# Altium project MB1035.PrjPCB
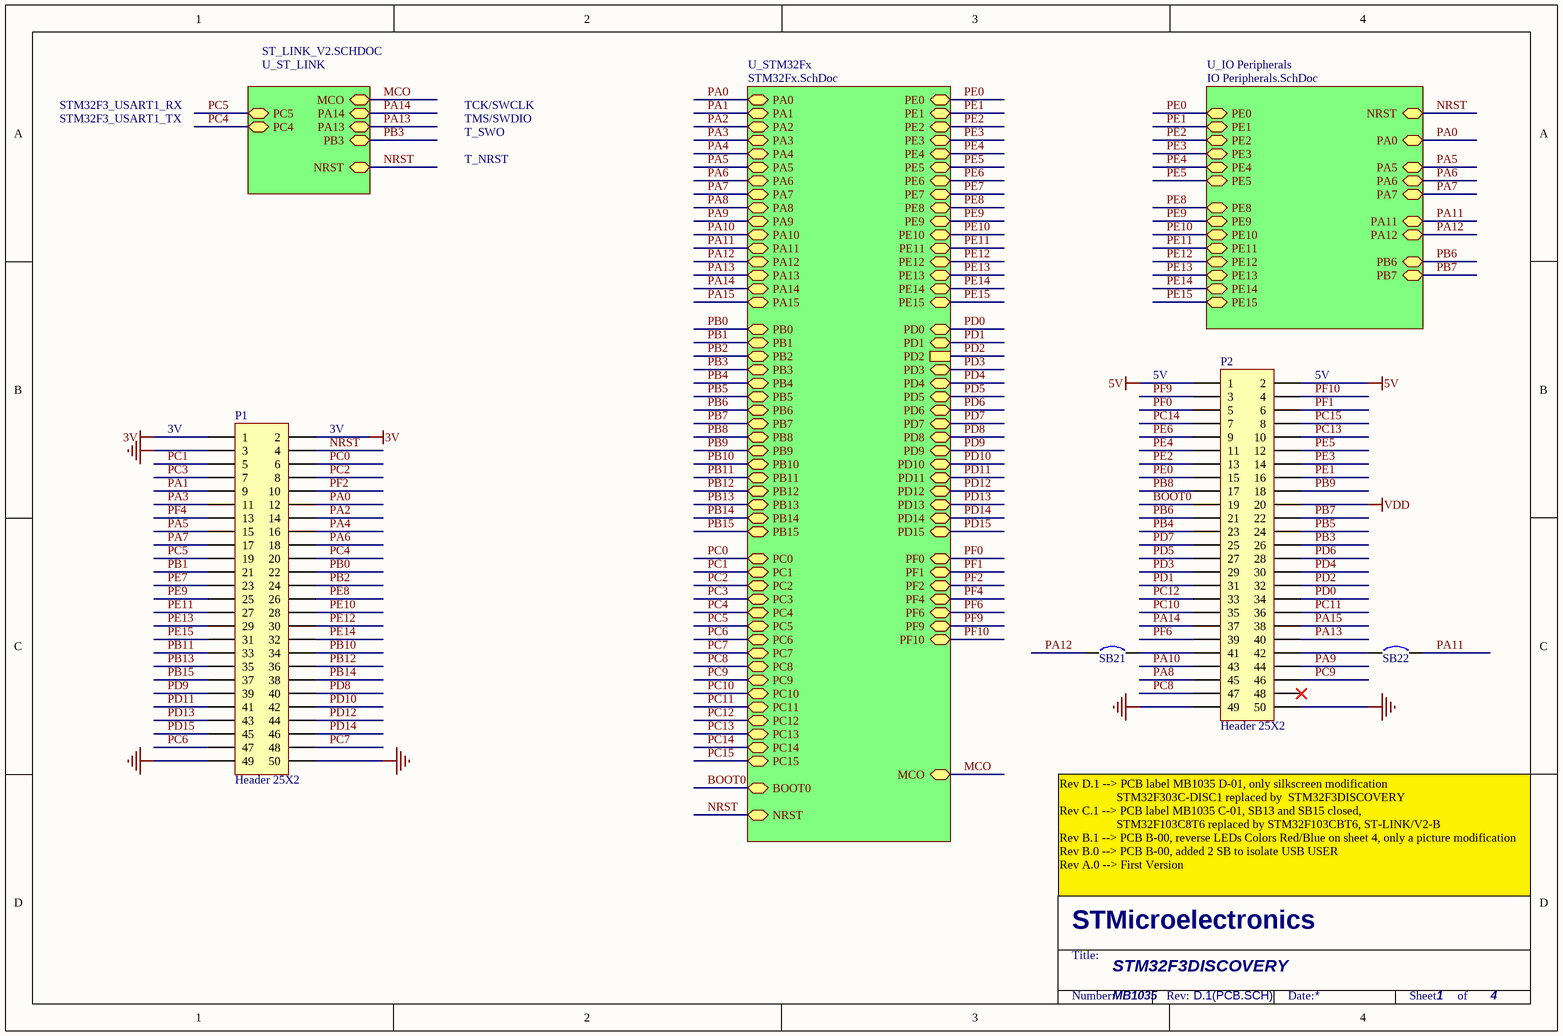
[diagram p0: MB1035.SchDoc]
4 sheets, 145 parts. Net scope: hierarchical (ports join the sheet entries above them; power ports are global).
Board file: MB1035B.PCBDOC
Sheets:
  MB1035.SchDoc
    U_ST_LINK = ST_LINK_V2.SCHDOC
    U_IO Peripherals = IO Peripherals.SchDoc
    U_STM32Fx = STM32Fx.SchDoc

## Sheet MB1035.SchDoc
size A4; DocumentNumber: 1; Revision: D.1(PCB.SCH); SheetNumber: 1; SheetTotal: 4; PageSetup: Record=PageOptions|CenterHorizontal=True|CenterVertical=True|PrintScale=1.00|XCorrection=1.00|YCorrection=1.00|PrintKind=1|BorderSize=5000000|LeftOffset=0|BottomOffset=0|Orientation=2|PaperLength=1000|PaperWidth=1000|Scale=100|PaperSource=15|PrintQuality=1200|MediaType=1|DitherType=10|PaperKind=A4|PrintScaleMode=1

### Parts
P1  Header 25X2  [HEAD25X2/2.54]
P2  Header 25X2  [HEAD25X2/2.54]
SB21  Circuit Breaker  [JP2_SMD]  (value not drawn)
SB22  Circuit Breaker  [JP2_SMD]  (value not drawn)

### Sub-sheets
U_IO Peripherals = IO Peripherals.SchDoc: PA0, NRST, PE0, PE1, PE3, PA5, PA7, PA6, PB6, PB7, PE4, PE5, PE2, PE8, PE15, PA11, PA12, PE9, PE10, PE11, PE12, PE13, PE14
U_ST_LINK = ST_LINK_V2.SCHDOC: PA13, PA14, NRST, PC5, PC4, PB3, MCO
U_STM32Fx = STM32Fx.SchDoc: PB8, PC5, PC4, PD2, BOOT0, NRST, PE0, PE1, PE2, PE3, PE4, PE5, PE6, PE7, PE8, PE9, PE10, PE11, PE12, PE13, PE14, PE15, PD0, PD1, PD3, PD4, PD5, PD6, PD7, PD8, PD9, PD10, PD11, PD12, PD13, PD14, PD15, PC15, PC14, PF1, PF0, MCO, PF2, PF4, PF6, PF9, PF10, PC0, PC1, PC2, PC3, PC6, PC7, PC8, PC9, PC10, PC11, PC12, PC13, PA0, PA1, PA2, PA3, PA4, PA5, PA6, PA7, PA8, PA9, PA10, PA11, PA12, PA13, PA14, PA15, PB0, PB1, PB2, PB3, PB4, PB5, PB6, PB7, PB9, PB10, PB11, PB12, PB13, PB14, PB15

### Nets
3V: P1.1 P1.2
5V: P2.1 P2.2
GND: P1.3 P1.49 P1.50 P2.49 P2.50
VDD: P2.20
BOOT0: P2.19 ; sheet U_STM32Fx/BOOT0
MCO: sheet U_ST_LINK/MCO, sheet U_STM32Fx/MCO
NRST: P1.4 ; sheet U_ST_LINK/NRST, sheet U_IO Peripherals/NRST, sheet U_STM32Fx/NRST
PA0: P1.12 ; sheet U_IO Peripherals/PA0, sheet U_STM32Fx/PA0
PA1: P1.9 ; sheet U_STM32Fx/PA1
PA2: P1.14 ; sheet U_STM32Fx/PA2
PA3: P1.11 ; sheet U_STM32Fx/PA3
PA4: P1.16 ; sheet U_STM32Fx/PA4
PA5: P1.15 ; sheet U_IO Peripherals/PA5, sheet U_STM32Fx/PA5
PA6: P1.18 ; sheet U_IO Peripherals/PA6, sheet U_STM32Fx/PA6
PA7: P1.17 ; sheet U_IO Peripherals/PA7, sheet U_STM32Fx/PA7
PA8: P2.45 ; sheet U_STM32Fx/PA8
PA9: P2.44 ; sheet U_STM32Fx/PA9
PA10: P2.43 ; sheet U_STM32Fx/PA10
PA11: SB22.2 ; sheet U_IO Peripherals/PA11, sheet U_STM32Fx/PA11
PA12: SB21.1 ; sheet U_IO Peripherals/PA12, sheet U_STM32Fx/PA12
PA13: P2.40 ; sheet U_ST_LINK/PA13, sheet U_STM32Fx/PA13
PA14: P2.37 ; sheet U_ST_LINK/PA14, sheet U_STM32Fx/PA14
PA15: P2.38 ; sheet U_STM32Fx/PA15
PB0: P1.22 ; sheet U_STM32Fx/PB0
PB1: P1.21 ; sheet U_STM32Fx/PB1
PB2: P1.24 ; sheet U_STM32Fx/PB2
PB3: P2.26 ; sheet U_ST_LINK/PB3, sheet U_STM32Fx/PB3
PB4: P2.23 ; sheet U_STM32Fx/PB4
PB5: P2.24 ; sheet U_STM32Fx/PB5
PB6: P2.21 ; sheet U_IO Peripherals/PB6, sheet U_STM32Fx/PB6
PB7: P2.22 ; sheet U_IO Peripherals/PB7, sheet U_STM32Fx/PB7
PB8: P2.17 ; sheet U_STM32Fx/PB8
PB9: P2.18 ; sheet U_STM32Fx/PB9
PB10: P1.34 ; sheet U_STM32Fx/PB10
PB11: P1.33 ; sheet U_STM32Fx/PB11
PB12: P1.36 ; sheet U_STM32Fx/PB12
PB13: P1.35 ; sheet U_STM32Fx/PB13
PB14: P1.38 ; sheet U_STM32Fx/PB14
PB15: P1.37 ; sheet U_STM32Fx/PB15
PC0: P1.6 ; sheet U_STM32Fx/PC0
PC1: P1.5 ; sheet U_STM32Fx/PC1
PC2: P1.8 ; sheet U_STM32Fx/PC2
PC3: P1.7 ; sheet U_STM32Fx/PC3
PC4: P1.20 ; sheet U_ST_LINK/PC4, sheet U_STM32Fx/PC4
PC5: P1.19 ; sheet U_ST_LINK/PC5, sheet U_STM32Fx/PC5
PC6: P1.47 ; sheet U_STM32Fx/PC6
PC7: P1.48 ; sheet U_STM32Fx/PC7
PC8: P2.47 ; sheet U_STM32Fx/PC8
PC9: P2.46 ; sheet U_STM32Fx/PC9
PC10: P2.35 ; sheet U_STM32Fx/PC10
PC11: P2.36 ; sheet U_STM32Fx/PC11
PC12: P2.33 ; sheet U_STM32Fx/PC12
PC13: P2.10 ; sheet U_STM32Fx/PC13
PC14: P2.7 ; sheet U_STM32Fx/PC14
PC15: P2.8 ; sheet U_STM32Fx/PC15
PD0: P2.34 ; sheet U_STM32Fx/PD0
PD1: P2.31 ; sheet U_STM32Fx/PD1
PD2: P2.32 ; sheet U_STM32Fx/PD2
PD3: P2.29 ; sheet U_STM32Fx/PD3
PD4: P2.30 ; sheet U_STM32Fx/PD4
PD5: P2.27 ; sheet U_STM32Fx/PD5
PD6: P2.28 ; sheet U_STM32Fx/PD6
PD7: P2.25 ; sheet U_STM32Fx/PD7
PD8: P1.40 ; sheet U_STM32Fx/PD8
PD9: P1.39 ; sheet U_STM32Fx/PD9
PD10: P1.42 ; sheet U_STM32Fx/PD10
PD11: P1.41 ; sheet U_STM32Fx/PD11
PD12: P1.44 ; sheet U_STM32Fx/PD12
PD13: P1.43 ; sheet U_STM32Fx/PD13
PD14: P1.46 ; sheet U_STM32Fx/PD14
PD15: P1.45 ; sheet U_STM32Fx/PD15
PE0: P2.15 ; sheet U_IO Peripherals/PE0, sheet U_STM32Fx/PE0
PE1: P2.16 ; sheet U_IO Peripherals/PE1, sheet U_STM32Fx/PE1
PE2: P2.13 ; sheet U_IO Peripherals/PE2, sheet U_STM32Fx/PE2
PE3: P2.14 ; sheet U_IO Peripherals/PE3, sheet U_STM32Fx/PE3
PE4: P2.11 ; sheet U_IO Peripherals/PE4, sheet U_STM32Fx/PE4
PE5: P2.12 ; sheet U_IO Peripherals/PE5, sheet U_STM32Fx/PE5
PE6: P2.9 ; sheet U_STM32Fx/PE6
PE7: P1.23 ; sheet U_STM32Fx/PE7
PE8: P1.26 ; sheet U_IO Peripherals/PE8, sheet U_STM32Fx/PE8
PE9: P1.25 ; sheet U_IO Peripherals/PE9, sheet U_STM32Fx/PE9
PE10: P1.28 ; sheet U_IO Peripherals/PE10, sheet U_STM32Fx/PE10
PE11: P1.27 ; sheet U_IO Peripherals/PE11, sheet U_STM32Fx/PE11
PE12: P1.30 ; sheet U_IO Peripherals/PE12, sheet U_STM32Fx/PE12
PE13: P1.29 ; sheet U_IO Peripherals/PE13, sheet U_STM32Fx/PE13
PE14: P1.32 ; sheet U_IO Peripherals/PE14, sheet U_STM32Fx/PE14
PE15: P1.31 ; sheet U_IO Peripherals/PE15, sheet U_STM32Fx/PE15
PF0: P2.5 ; sheet U_STM32Fx/PF0
PF1: P2.6 ; sheet U_STM32Fx/PF1
PF2: P1.10 ; sheet U_STM32Fx/PF2
PF4: P1.13 ; sheet U_STM32Fx/PF4
PF6: P2.39 ; sheet U_STM32Fx/PF6
PF9: P2.3 ; sheet U_STM32Fx/PF9
PF10: P2.4 ; sheet U_STM32Fx/PF10
NetP2_41: P2.41 SB21.2
NetP2_42: P2.42 SB22.1

Not connected (* = marked no-connect by the designer): P2 48*

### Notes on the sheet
- STM32F3_USART1_RX
- TCK/SWCLK
- STM32F3_USART1_TX
- TMS/SWDIO
- T_SWO
- T_NRST
- 5V
- (near P2) 5V
- 3V
- (near P1) 3V
- Rev D.1 --> PCB label MB1035 D-01, only silkscreen modification
  STM32F303C-DISC1 replaced by  STM32F3DISCOVERY
  Rev C.1 --> PCB label MB1035 C-01, SB13 and SB15 closed,
  STM32F103C8T6 replaced by STM32F103CBT6, ST-LINK/V2-B
  Rev B.1 --> PCB B-00, reverse LEDs Colors Red/Blue on sheet 4, only a picture modification
  Rev B.0 --> PCB B-00, added 2 SB to isolate USB USER
  Rev A.0 --> First Version
- STM32F3DISCOVERY
- MB1035
- 1

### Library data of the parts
P1 P2 = Header 25X2: Header, 25-Pin, Dual row
SB21 SB22 = Circuit Breaker: Solder: NO

## Sheet ST_LINK_V2.SCHDOC
size A4; DocumentNumber: 2; Revision: D.1(PCB.SCH); SheetNumber: 2; SheetTotal: 4
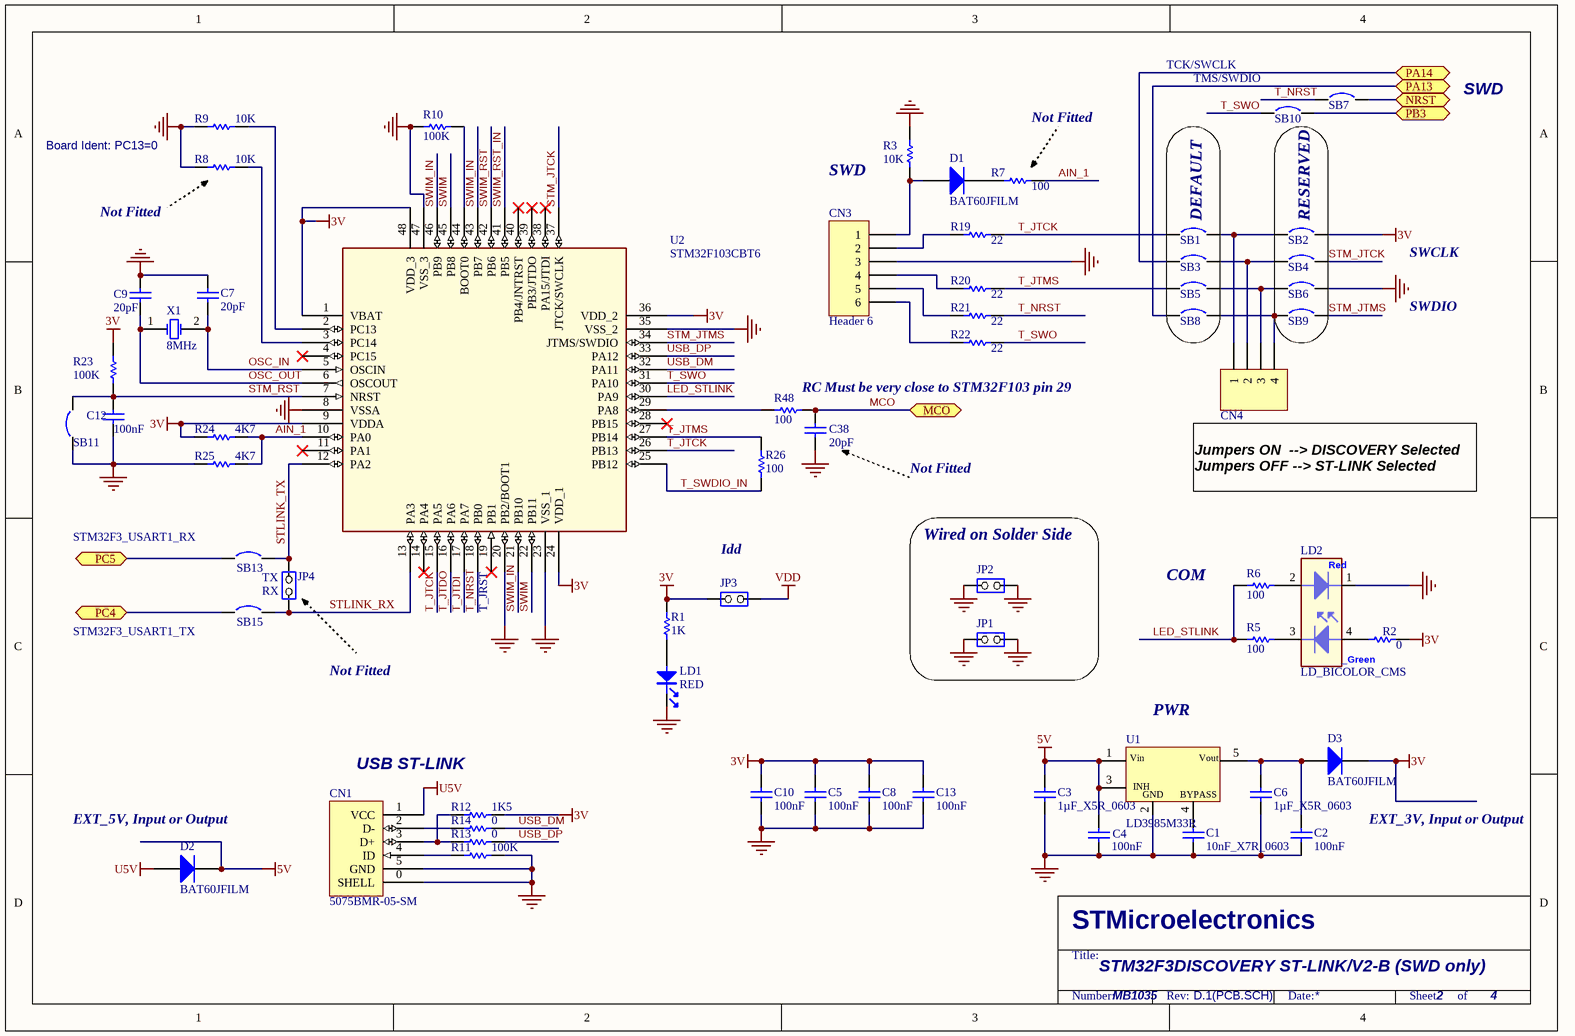
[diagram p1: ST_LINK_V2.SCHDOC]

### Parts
C1  10nF_X7R_0603  [0603C]
C2  100nF  [0603C]
C3  1µF_X5R_0603  [0603C]
C4  100nF  [0603C]
C5  100nF  [0402C]
C6  1µF_X5R_0603  [0603C]
C7  20pF  [0402C]
C8  100nF  [0402C]
C9  20pF  [0402C]
C10  100nF  [0402C]
C12  100nF  [0402C]
C13  100nF  [0402C]
C38  20pF  [0402C]
CN1  5075BMR-05-SM  [USB-MINI-B-SMD]
CN3  Header 6  [HDR1X6]
CN4  Header 4  [Header 4]  (value not drawn)
D1  BAT60JFILM  [SOD323/A]
D2  BAT60JFILM  [SOD323/A]
D3  BAT60JFILM  [SOD323/A]
JP1  (no value)  [SIP2/2.54]
JP2  (no value)  [SIP2/2.54]
JP3  (no value)  [SIP2/2.54]
JP4  JP2  [SIP2/2.54]  (value not drawn)
LD1  RED  [0603D]
LD2  LD_BICOLOR_CMS  [HSMF-A201]
R1  1K  [0402R]
R2  0  [0402R]
R3  10K  [0402R]
R5  100  [0402R]
R6  100  [0402R]
R7  100  [0402R]
R8  10K  [0402R]
R9  10K  [0402R]
R10  100K  [0402R]
R11  100K  [0402R]
R12  1K5  [0402R]
R13  0  [0402R]
R14  0  [0402R]
R19  22  [0402R]
R20  22  [0402R]
R21  22  [0402R]
R22  22  [0402R]
R23  100K  [0402R]
R24  4K7  [0402R]
R25  4K7  [0402R]
R26  100  [0402R]
R48  100  [0402R]
SB1  Circuit Breaker  [JP2_SMD]  (value not drawn)
SB2  Circuit Breaker  [JP2_SMD]  (value not drawn)
SB3  Circuit Breaker  [JP2_SMD]  (value not drawn)
SB4  Circuit Breaker  [JP2_SMD]  (value not drawn)
SB5  Circuit Breaker  [JP2_SMD]  (value not drawn)
SB6  Circuit Breaker  [JP2_SMD]  (value not drawn)
SB7  Circuit Breaker  [JP2_SMD]  (value not drawn)
SB8  Circuit Breaker  [JP2_SMD]  (value not drawn)
SB9  Circuit Breaker  [JP2_SMD]  (value not drawn)
SB10  Circuit Breaker  [JP2_SMD]  (value not drawn)
SB11  Circuit Breaker  [JP2_SMD]  (value not drawn)
SB13  Circuit Breaker  [JP2_SMD]  (value not drawn)
SB15  Circuit Breaker  [JP2_SMD]  (value not drawn)
U1  LD3985M33R  [SOT-23-5L]
U2  STM32F103CBT6  [QFP48 7x7]
X1  8MHz  [XTAL1]

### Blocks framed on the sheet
DEFAULT: SB1 SB3 SB5 SB8
RESERVED: SB2 SB4 SB6 SB9
Wired on Solder Side: JP1 JP2

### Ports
MCO, NRST, PA13, PA14, PB3, PC4, PC5

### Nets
3V: C5.2 C8.1 C10.2 C13.2 D3.2(K) JP3.1(COMMON) R1.2 R2.2 R12.2 R23.2 R24.1 SB2.2 U2.1(VBAT) U2.9(VDDA) U2.24(VDD_1) U2.36(VDD_2) U2.48(VDD_3)
5V: C3.2 C4.2 D2.2(K) U1.1(Vin) U1.3(CE)
GND: C1.1 C2.1 C3.1 C4.1 C5.1 C6.2 C7.1 C8.2 C9.1 C10.1 C12.1 C13.1 C38.2 CN1.0(SHELL) CN1.5(GND) CN3.3 JP1.1(COMMON) JP1.2(NO) JP2.1(COMMON) JP2.2(NO) LD1.2 LD2.1 R3.2 R8.1 R9.1 R10.1 R11.2 R25.1 SB6.2 SB11.1 U1.2(GND) U2.8(VSSA) U2.20(PB2/BOOT1) U2.23(VSS_1) U2.35(VSS_2) U2.47(VSS_3)
U5V: CN1.1(VCC) D2.1(A)
VDD: JP3.2(NO)
AIN_1: R7.2 R24.2 R25.2 U2.10(PA0)
LED_STLINK: R5.1 R6.1 U2.30(PA9)
MCO: C38.1 R48.2 ; port MCO
NRST: SB7.2 ; port NRST
OSC_IN: C7.2 U2.5(OSCIN) X1.2(OSC2)
OSC_OUT: C9.2 U2.6(OSCOUT) X1.1(OSC1)
PA13: SB8.1 ; port PA13
PA14: SB3.1 ; port PA14
PB3: SB10.2 ; port PB3
PC4: SB15.1 ; port PC4
PC5: SB13.1 ; port PC5
STLINK_RX: JP4.1(COMMON) SB15.2 U2.13(PA3)
STLINK_TX: JP4.2(NO) SB13.2 U2.12(PA2)
STM_JTCK: SB4.2 U2.37(JTCK/SWCLK)
STM_JTMS: SB9.2 U2.34(JTMS/SWDIO)
STM_RST: C12.2 R23.1 SB11.2 U2.7(NRST)
SWIM: U2.22(PB11) U2.45(PB8)
SWIM_IN: U2.21(PB10) U2.43(PB7) U2.46(PB9)
SWIM_RST: U2.42(PB6)
SWIM_RST_IN: U2.41(PB5)
T_JTCK: R19.2 SB1.1 U2.15(PA5) U2.26(PB13)
T_JTDI: U2.17(PA7)
T_JTDO: U2.16(PA6)
T_JTMS: R20.2 R26.2 SB5.1 U2.27(PB14)
T_NRST: R21.2 SB7.1 U2.18(PB0)
T_SWDIO_IN: R26.1 U2.25(PB12)
T_SWO: R22.2 SB10.1 U2.31(PA10)
USB_DM: R14.2 U2.32(PA11)
USB_DP: R13.2 U2.33(PA12)
NetC1_2: C1.2 U1.4(BYPASS)
NetC2_2: C2.2 C6.1 D3.1(A) U1.5(Vout)
NetCN1_2: CN1.2(D-) R14.1
NetCN1_3: CN1.3(D+) R12.1 R13.1
NetCN1_4: CN1.4(ID) R11.1
NetCN3_1: CN3.1 D1.1(A) R3.1
NetCN3_2: CN3.2 R19.1
NetCN3_4: CN3.4 R20.1
NetCN3_5: CN3.5 R21.1
NetCN3_6: CN3.6 R22.1
NetCN4_1: CN4.1 SB1.2 SB2.1
NetCN4_2: CN4.2 SB3.2 SB4.1
NetCN4_3: CN4.3 SB5.2 SB6.1
NetCN4_4: CN4.4 SB8.2 SB9.1
NetD1_2: D1.2(K) R7.1
NetLD1_1: LD1.1 R1.1
NetLD2_2: LD2.2 R6.2
NetLD2_3: LD2.3 R5.2
NetLD2_4: LD2.4 R2.1
NetR8_2: R8.2 U2.3(PC14)
NetR9_2: R9.2 U2.2(PC13)
NetR10_2: R10.2 U2.44(BOOT0)
NetR48_1: R48.1 U2.29(PA8)

Not connected (* = marked no-connect by the designer): U2 4(PC15)* 11(PA1)* 14(PA4)* 19(PB1)* 28(PB15)* 38(PA15/JTDI)* 39(PB3/JTDO)* 40(PB4/JNTRST)*

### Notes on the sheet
- TCK/SWCLK
- (near SB10) TMS/SWDIO
- SWD
- Board Ident: PC13=0
- Not Fitted
- SWCLK
- SWDIO
- (near R48) RC Must be very close to STM32F103 pin 29
- Jumpers ON  --> DISCOVERY Selected
  Jumpers OFF --> ST-LINK Selected
- STM32F3_USART1_RX
- TX
- (near JP3) Idd
- COM
- STM32F3_USART1_TX
- RX
- (near U2) T_JRST
- (near U1) PWR
- USB ST-LINK
- (near D2) EXT_5V, Input or Output
- EXT_3V, Input or Output
- STM32F3DISCOVERY ST-LINK/V2-B (SWD only)
- MB1035

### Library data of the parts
C1 = CAP SMD 0603  X7R 10000PF 50V 10%: 0603  X7R 10NF; Order code RS: 2040779; Rated voltage: 50V; Tolerance: 10%
C2 C4 C5 C7-C10 C12 C13 = Cap: Capacitor
C3 C6 = CAP SMD 0603  X5R 1µF 25V 10%: 0603  X5R 1µF; Rated voltage: 25V; Tolerance: 10%
C38 = Cap: Capacitor; Fitted: NO
CN1 = USB-MINI-typeB connector
CN3 = Header 6: Header, 6-Pin
CN4 = Header 4: Header, 4-Pin
D1-D3 = BAT60JFILM: Manuf_1: STM; Code - JEDEC: DO-214-AB; Provided: ST
JP1-JP3 = JP2
JP4 = JP2: Fitted: NO
LD1 = PHOTO
LD2 = LD_BICOLOR_CMS: Bicolor Led; Manuf_Part_1: HSMF-A201-A00J1; Manuf_1: Avago Technologies; Ref St: xxxxxx; cap_dec: ----
R1-R3 R5 R6 R9-R12 R19-R26 R48 = res1: Resistor
R7 R8 = res1: Resistor; Fitted: NO
R13 R14 = res1: Resistor; Value: 1K5
SB1 SB3 SB5 SB8 SB10 SB11 = Circuit Breaker: Solder: NO
SB2 SB4 SB6 SB7 SB9 = Circuit Breaker: Solder: YES
U1 = LD3985M33R: Ultra low drop-low noise BiCMOS voltage, regulators low ESR capacitors compatible; Manuf_1: STM; Provided: ST; Ref St: 9176161
U2 = STM32F103CBT6: Medium-density performance line ARM-based 32-bit MCU with 128KB Flash; Manuf_1: STM; Ref St: xxxxxxxx; Provided: ST; ECCN_US/EU: 3A991A2/NEC
X1 = XTAL: Crystal Oscillator

## Sheet IO Peripherals.SchDoc
size A4; DocumentNumber: 6; Revision: D.1(PCB.SCH); SheetNumber: 4; SheetTotal: 4
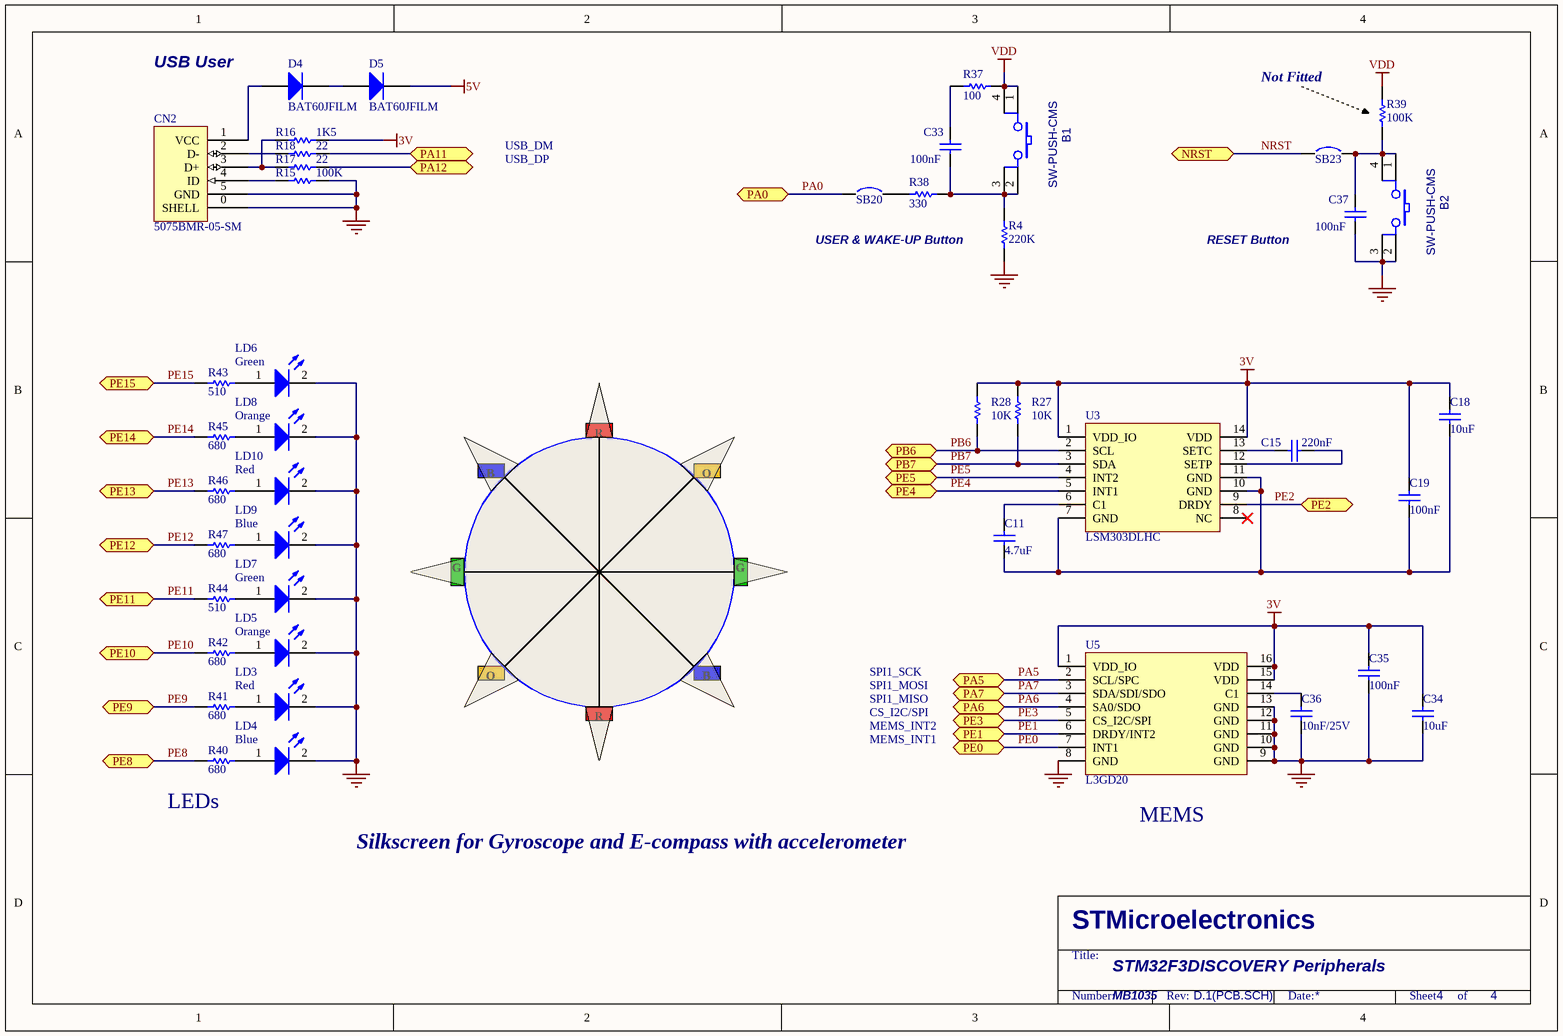
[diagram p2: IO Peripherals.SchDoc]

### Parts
B1  SW-PUSH-CMS  [BP1CMS]
B2  SW-PUSH-CMS  [BP1CMS]
C11  4.7uF  [0603C]
C15  220nF  [0603C]
C18  10uF  [0603C]
C19  100nF  [0603C]
C33  100nF  [0603C]
C34  10uF  [0603C]
C35  100nF  [0603C]
C36  10nF/25V  [0603C]
C37  100nF  [0603C]
CN2  5075BMR-05-SM  [USB-MINI-B-SMD]
D4  BAT60JFILM  [SOD323/A]
D5  BAT60JFILM  [SOD323/A]
LD3  Red  [0603D]
LD4  Blue  [0603D]
LD5  Orange  [0603D]
LD6  Green  [0603D]
LD7  Green  [0603D]
LD8  Orange  [0603D]
LD9  Blue  [0603D]
LD10  Red  [0603D]
R4  220K  [0603R]
R15  100K  [0402R]
R16  1K5  [0402R]
R17  22  [0402R]
R18  22  [0402R]
R27  10K  [0402R]
R28  10K  [0402R]
R37  100  [0402R]
R38  330  [0402R]
R39  100K  [0402R]
R40  680  [0603R]
R41  680  [0603R]
R42  680  [0603R]
R43  510  [0603R]
R44  510  [0603R]
R45  680  [0603R]
R46  680  [0603R]
R47  680  [0603R]
SB20  Circuit Breaker  [JP2_SMD]  (value not drawn)
SB23  Circuit Breaker  [JP2_SMD]  (value not drawn)
U3  LSM303DLHC  [LGA14]
U5  L3GD20  [LGA16]

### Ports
NRST, PA0, PA5, PA6, PA7, PA11, PA12, PB6, PB7, PE0, PE1, PE2, PE3, PE4, PE5, PE8, PE9, PE10, PE11, PE12, PE13, PE14, PE15

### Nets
3V: C18.2 C19.2 C34.2 C35.2 R16.2 R27.1 R28.1 U3.1(VDD_IO) U3.14(VDD) U5.1(VDD_IO) U5.15(VDD) U5.16(VDD)
5V: D5.2(K)
GND: B2.2 B2.3 C34.1 C35.1 C36.1 C37.1 CN2.0(SHELL) CN2.5(GND) LD3.2(K) LD4.2(K) LD5.2(K) LD6.2(K) LD7.2(K) LD8.2(K) LD9.2(K) LD10.2(K) R4.1 R15.2 U5.8(GND) U5.9(GND) U5.10(GND) U5.11(GND) U5.12(GND) U5.13(GND)
VDD: B1.1 B1.4 R37.2 R39.2
NRST: SB23.1 ; port NRST
PA0: SB20.1 ; port PA0
PA5: U5.2(SCL/SPC) ; port PA5
PA6: U5.4(SA0/SDO) ; port PA6
PA7: U5.3(SDA/SDI/SDO) ; port PA7
PA11: R18.2 ; port PA11
PA12: R17.2 ; port PA12
PB6: R28.2 U3.2(SCL) ; port PB6
PB7: R27.2 U3.3(SDA) ; port PB7
PE0: U5.7(INT1) ; port PE0
PE1: U5.6(DRDY/INT2) ; port PE1
PE2: U3.9(DRDY) ; port PE2
PE3: U5.5(CS_I2C/SPI) ; port PE3
PE4: U3.5(INT1) ; port PE4
PE5: U3.4(INT2) ; port PE5
PE8: R40.2 ; port PE8
PE9: R41.2 ; port PE9
PE10: R42.2 ; port PE10
PE11: R44.2 ; port PE11
PE12: R47.2 ; port PE12
PE13: R46.2 ; port PE13
PE14: R45.2 ; port PE14
PE15: R43.2 ; port PE15
NetB1_2: B1.2 B1.3 C33.1 R4.2 R38.2
NetB2_1: B2.1 B2.4 C37.2 R39.1 SB23.2
NetC11_1: C11.1 C18.1 C19.1 U3.7(GND) U3.10(GND) U3.11(GND)
NetC11_2: C11.2 U3.6(C1)
NetC15_1: C15.1 U3.13(SETC)
NetC15_2: C15.2 U3.12(SETP)
NetC33_2: C33.2 R37.1
NetC36_2: C36.2 U5.14(C1)
NetCN2_1: CN2.1(VCC) D4.1(A)
NetCN2_2: CN2.2(D-) R18.1
NetCN2_3: CN2.3(D+) R16.1 R17.1
NetCN2_4: CN2.4(ID) R15.1
NetD4_2: D4.2(K) D5.1(A)
NetLD3_1: LD3.1(A) R41.1
NetLD4_1: LD4.1(A) R40.1
NetLD5_1: LD5.1(A) R42.1
NetLD6_1: LD6.1(A) R43.1
NetLD7_1: LD7.1(A) R44.1
NetLD8_1: LD8.1(A) R45.1
NetLD9_1: LD9.1(A) R47.1
NetLD10_1: LD10.1(A) R46.1
NetR38_1: R38.1 SB20.2

Not connected (* = marked no-connect by the designer): U3 8(NC)*

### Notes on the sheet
- USB User
- Not Fitted
- USB_DM
- USB_DP
- USER & WAKE-UP Button
- RESET Button
- N
- R
- B
- O
- W
- G
- E
- SPI1_MOSI
- SPI1_SCK
- SPI1_MISO
- CS_I2C/SPI
- S
- MEMS_INT1
- MEMS_INT2
- (near R40) LEDs
- Silkscreen for Gyroscope and E-compass with accelerometer
- (near U5) MEMS
- STM32F3DISCOVERY Peripherals
- MB1035

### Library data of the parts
B1 B2 = SW-PUSH-CMS: Non-Open Push-Button 0.1A 24V; Manuf_1: FARNELL; Manuf_Part_1: 535-930; Ref St: 9180120; cap_dec: ---
C11 C15 C18 C34 C36 = CAP: Capacitor; Value: 100nF
C19 C33 C35 C37 = CAP: Capacitor
CN2 = USB-MINI-typeB connector
D4 D5 = BAT60JFILM: as D1 on sheet ST_LINK_V2
LD3-LD10 = LED2: Typical RED, GREEN, YELLOW, AMBER GaAs LED
R4 = res1: Resistor; Value: 10K
R15 R16 R27 R28 R38 = res1: Resistor
R17 R18 = res1: Resistor; Value: 1K5
R37 = res1: Resistor; Value: 330
R39 = res1: Resistor; Fitted: NO
R40-R47 = Res1: Resistor; Value: 1K
SB20 SB23 = Circuit Breaker: Solder: YES
U3 = LSM303DLHC: Ultra compact high performance e-compass 3D accelerometer and 3D magnetometer module; Manuf_1: STM; Manuf_Part_1: LSM303DLHCTR; Provided: ST; ref St: xxxxxxxxxx
U5 = L3GD20: MEMS motion sensor three-axis digital output gyroscopeelerometer; Manuf_1: STM; Manuf_Part_1: L3GD20TR; Provided: ST; ref St: xxxxxxxx

## Sheet STM32Fx.SchDoc
size A4; DocumentNumber: 3; Revision: D.1(PCB.SCH); SheetNumber: 3; SheetTotal: 4
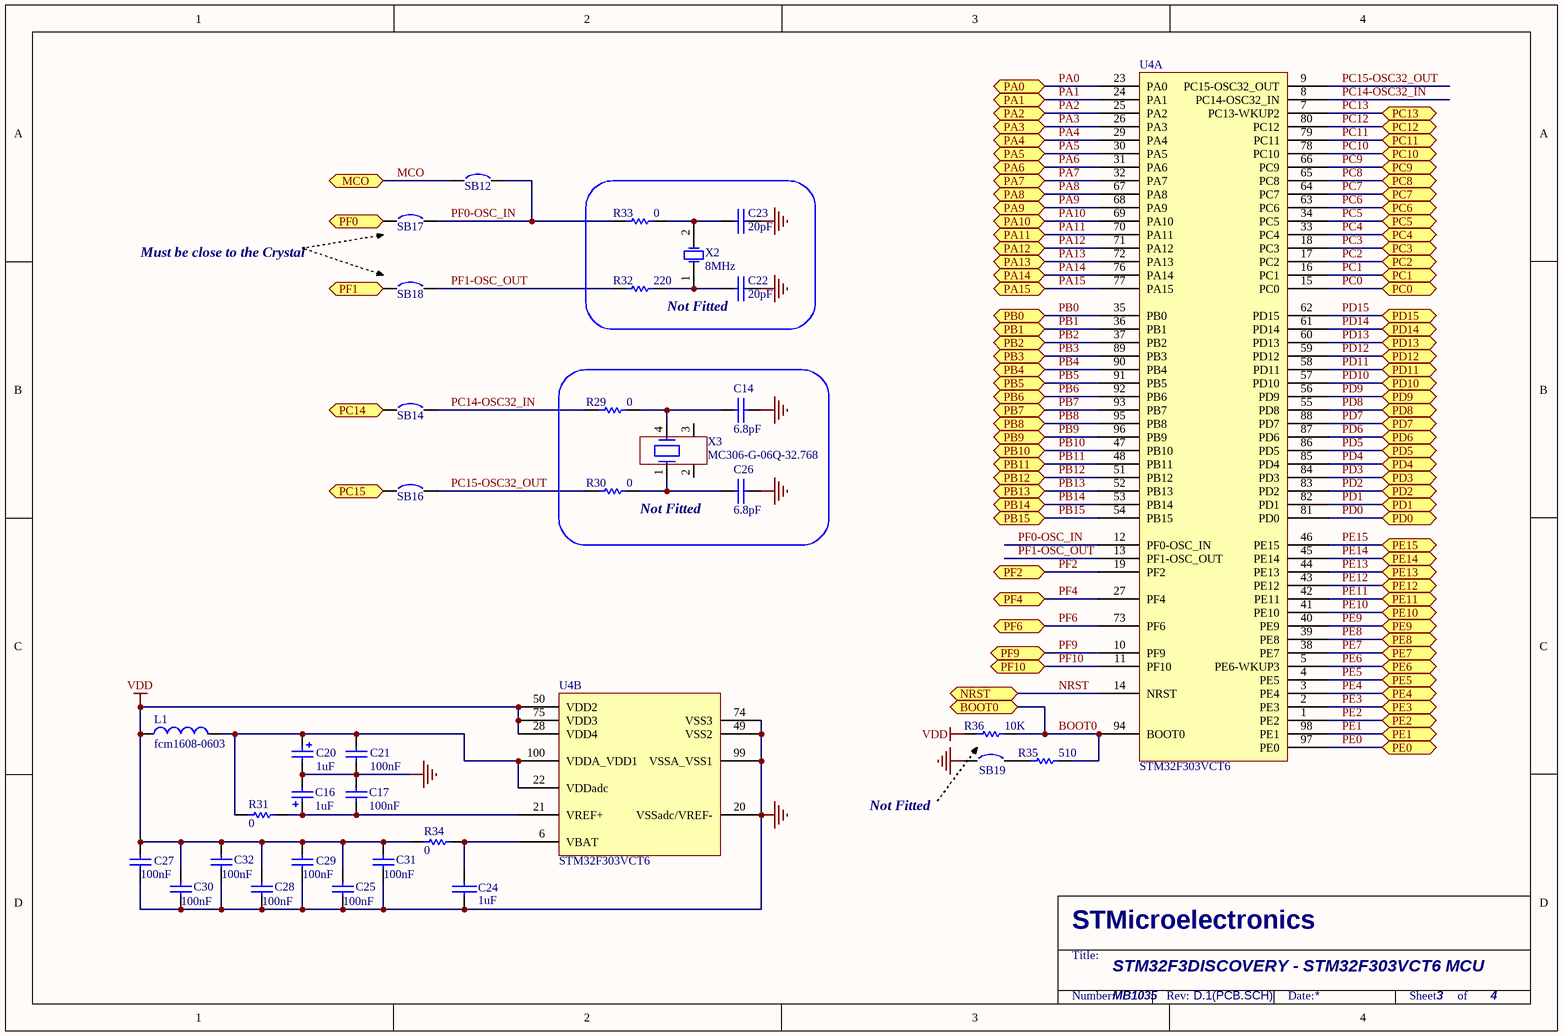
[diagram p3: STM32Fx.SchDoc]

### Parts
C14  6.8pF  [0603C]
C16  1uF  [CASE-AA]
C17  100nF  [0603C]
C20  1uF  [CASE-AA]
C21  100nF  [0603C]
C22  20pF  [0603C]
C23  20pF  [0603C]
C24  1uF  [0603C]
C25  100nF  [0603C]
C26  6.8pF  [0603C]
C27  100nF  [0603C]
C28  100nF  [0603C]
C29  100nF  [0603C]
C30  100nF  [0603C]
C31  100nF  [0603C]
C32  100nF  [0603C]
L1  fcm1608-0603  [0603L]
R29  0  [0402R]
R30  0  [0402R]
R31  0  [0402R]
R32  220  [0402R]
R33  0  [0402R]
R34  0  [0402R]
R35  510  [0402R]
R36  10K  [0402R]
SB12  Circuit Breaker  [JP2_SMD]  (value not drawn)
SB14  Circuit Breaker  [JP2_SMD]  (value not drawn)
SB16  Circuit Breaker  [JP2_SMD]  (value not drawn)
SB17  Circuit Breaker  [JP2_SMD]  (value not drawn)
SB18  Circuit Breaker  [JP2_SMD]  (value not drawn)
SB19  Circuit Breaker  [JP2_SMD]  (value not drawn)
U4  STM32F303VCT6  [LQFP100]  (parts A,B of 2)
X2  8MHz  [XTAL1]
X3  MC306-G-06Q-32.768  [MC306-CRYSTAL]

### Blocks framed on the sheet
Not Fitted: C22 C23 R32 R33 X2
Not Fitted: C14 C26 R29 R30 X3

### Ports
BOOT0, MCO, NRST, PA0, PA1, PA2, PA3, PA4, PA5, PA6, PA7, PA8, PA9, PA10, PA11, PA12, PA13, PA14, PA15, PB0, PB1, PB2, PB3, PB4, PB5, PB6, PB7, PB8, PB9, PB10, PB11, PB12, PB13, PB14, PB15, PC0, PC1, PC2, PC3, PC4, PC5, PC6, PC7, PC8, PC9, PC10, PC11, PC12, PC13, PC14, PC15, PD0, PD1, PD2, PD3, PD4, PD5, PD6, PD7, PD8, PD9, PD10, PD11, PD12, PD13, PD14, PD15, PE0, PE1, PE2, PE3, PE4, PE5, PE6, PE7, PE8, PE9, PE10, PE11, PE12, PE13, PE14, PE15, PF0, PF1, PF2, PF4, PF6, PF9, PF10

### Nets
GND: C14.2 C16.2 C17.1 C20.2 C21.1 C22.1 C23.1 C24.2 C25.1 C26.2 C27.1 C28.1 C29.1 C30.1 C31.2 C32.2 SB19.1 U4.20(VSSadc/VREF-) U4.49(VSS2) U4.74(VSS3) U4.99(VSSA_VSS1)
VDD: C25.2 C27.2 C28.2 C29.2 C30.2 C31.1 C32.1 L1.1 R34.2 R36.1 U4.28(VDD4) U4.50(VDD2) U4.75(VDD3)
BOOT0: R35.2 R36.2 U4.94(BOOT0) ; port BOOT0
MCO: SB12.1 ; port MCO
NRST: U4.14(NRST) ; port NRST
PA0: U4.23(PA0) ; port PA0
PA1: U4.24(PA1) ; port PA1
PA2: U4.25(PA2) ; port PA2
PA3: U4.26(PA3) ; port PA3
PA4: U4.29(PA4) ; port PA4
PA5: U4.30(PA5) ; port PA5
PA6: U4.31(PA6) ; port PA6
PA7: U4.32(PA7) ; port PA7
PA8: U4.67(PA8) ; port PA8
PA9: U4.68(PA9) ; port PA9
PA10: U4.69(PA10) ; port PA10
PA11: U4.70(PA11) ; port PA11
PA12: U4.71(PA12) ; port PA12
PA13: U4.72(PA13) ; port PA13
PA14: U4.76(PA14) ; port PA14
PA15: U4.77(PA15) ; port PA15
PB0: U4.35(PB0) ; port PB0
PB1: U4.36(PB1) ; port PB1
PB2: U4.37(PB2) ; port PB2
PB3: U4.89(PB3) ; port PB3
PB4: U4.90(PB4) ; port PB4
PB5: U4.91(PB5) ; port PB5
PB6: U4.92(PB6) ; port PB6
PB7: U4.93(PB7) ; port PB7
PB8: U4.95(PB8) ; port PB8
PB9: U4.96(PB9) ; port PB9
PB10: U4.47(PB10) ; port PB10
PB11: U4.48(PB11) ; port PB11
PB12: U4.51(PB12) ; port PB12
PB13: U4.52(PB13) ; port PB13
PB14: U4.53(PB14) ; port PB14
PB15: U4.54(PB15) ; port PB15
PC0: U4.15(PC0) ; port PC0
PC1: U4.16(PC1) ; port PC1
PC2: U4.17(PC2) ; port PC2
PC3: U4.18(PC3) ; port PC3
PC4: U4.33(PC4) ; port PC4
PC5: U4.34(PC5) ; port PC5
PC6: U4.63(PC6) ; port PC6
PC7: U4.64(PC7) ; port PC7
PC8: U4.65(PC8) ; port PC8
PC9: U4.66(PC9) ; port PC9
PC10: U4.78(PC10) ; port PC10
PC11: U4.79(PC11) ; port PC11
PC12: U4.80(PC12) ; port PC12
PC13: U4.7(PC13-WKUP2) ; port PC13
PC14: SB14.1 ; port PC14
PC14-OSC32_IN: R29.1 SB14.2 U4.8(PC14-OSC32_IN)
PC15: SB16.1 ; port PC15
PC15-OSC32_OUT: R30.1 SB16.2 U4.9(PC15-OSC32_OUT)
PD0: U4.81(PD0) ; port PD0
PD1: U4.82(PD1) ; port PD1
PD2: U4.83(PD2) ; port PD2
PD3: U4.84(PD3) ; port PD3
PD4: U4.85(PD4) ; port PD4
PD5: U4.86(PD5) ; port PD5
PD6: U4.87(PD6) ; port PD6
PD7: U4.88(PD7) ; port PD7
PD8: U4.55(PD8) ; port PD8
PD9: U4.56(PD9) ; port PD9
PD10: U4.57(PD10) ; port PD10
PD11: U4.58(PD11) ; port PD11
PD12: U4.59(PD12) ; port PD12
PD13: U4.60(PD13) ; port PD13
PD14: U4.61(PD14) ; port PD14
PD15: U4.62(PD15) ; port PD15
PE0: U4.97(PE0) ; port PE0
PE1: U4.98(PE1) ; port PE1
PE2: U4.1(PE2) ; port PE2
PE3: U4.2(PE3) ; port PE3
PE4: U4.3(PE4) ; port PE4
PE5: U4.4(PE5) ; port PE5
PE6: U4.5(PE6-WKUP3) ; port PE6
PE7: U4.38(PE7) ; port PE7
PE8: U4.39(PE8) ; port PE8
PE9: U4.40(PE9) ; port PE9
PE10: U4.41(PE10) ; port PE10
PE11: U4.42(PE11) ; port PE11
PE12: U4.43(PE12) ; port PE12
PE13: U4.44(PE13) ; port PE13
PE14: U4.45(PE14) ; port PE14
PE15: U4.46(PE15) ; port PE15
PF0: SB17.1 ; port PF0
PF0-OSC_IN: R33.1 SB12.2 SB17.2 U4.12(PF0-OSC_IN)
PF1: SB18.1 ; port PF1
PF1-OSC_OUT: R32.1 SB18.2 U4.13(PF1-OSC_OUT)
PF2: U4.19(PF2) ; port PF2
PF4: U4.27(PF4) ; port PF4
PF6: U4.73(PF6) ; port PF6
PF9: U4.10(PF9) ; port PF9
PF10: U4.11(PF10) ; port PF10
NetC14_1: C14.1 R29.2 X3.4
NetC16_1: C16.1 C17.2 R31.1 U4.21(VREF+)
NetC20_1: C20.1 C21.2 L1.2 R31.2 U4.22(VDDadc) U4.100(VDDA_VDD1)
NetC22_2: C22.2 R32.2 X2.1(OSC1)
NetC23_2: C23.2 R33.2 X2.2(OSC2)
NetC24_1: C24.1 R34.1 U4.6(VBAT)
NetC26_1: C26.1 R30.2 X3.1
NetR35_1: R35.1 SB19.2

Not connected (* = marked no-connect by the designer): X3 2 3

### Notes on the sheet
- Must be close to the Crystal
- Not Fitted
- STM32F3DISCOVERY - STM32F303VCT6 MCU
- MB1035

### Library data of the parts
C14 C22 C23 C26 = CAP: Capacitor; Fitted: NO
C16 C20 = Cap Pol1: Polarized Capacitor (Radial); Value: 10uF
C17 C21 C25 C27-C32 = Cap: Capacitor
C24 = CAP: Capacitor
L1 = Inductor: Value: 100uH
R29 R30 R32 R33 = res1: Resistor; Value: 1K5; Fitted: NO
R31 R34 = Res1: Resistor; Value: 1K
R35 = res1: Resistor; Value: 10K
R36 = res1: Resistor; Fitted: NO
SB12 SB14 SB16 SB18 SB19 = Circuit Breaker: Solder: YES
SB17 = Circuit Breaker: Solder: NO
U4 = STM32F303VCT6: STM32F303VCT6 (Manta-Edge); Manuf_1: STM; Provided: ST
X2 = XTAL: Crystal Oscillator; Fitted: NO
X3 = MC306: Fitted: NO

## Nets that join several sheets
3V: MB1035 (P1.1 P1.2), ST_LINK_V2 (17 pins), IO Peripherals (12 pins)
5V: MB1035 (P2.1 P2.2), ST_LINK_V2 (5 pins), IO Peripherals (D5.2)
GND: MB1035 (5 pins), ST_LINK_V2 (36 pins), IO Peripherals (24 pins), STM32Fx (21 pins)
VDD: MB1035 (P2.20), ST_LINK_V2 (JP3.2), IO Peripherals (B1.1 B1.4 R37.2 R39.2), STM32Fx (13 pins)
BOOT0: MB1035 (P2.19), STM32Fx (R35.2 R36.2 U4.94)
MCO: ST_LINK_V2 (C38.1 R48.2), STM32Fx (SB12.1)
NRST: MB1035 (P1.4), ST_LINK_V2 (SB7.2), IO Peripherals (SB23.1), STM32Fx (U4.14)
PA0: MB1035 (P1.12), IO Peripherals (SB20.1), STM32Fx (U4.23)
PA1: MB1035 (P1.9), STM32Fx (U4.24)
PA2: MB1035 (P1.14), STM32Fx (U4.25)
PA3: MB1035 (P1.11), STM32Fx (U4.26)
PA4: MB1035 (P1.16), STM32Fx (U4.29)
PA5: MB1035 (P1.15), IO Peripherals (U5.2), STM32Fx (U4.30)
PA6: MB1035 (P1.18), IO Peripherals (U5.4), STM32Fx (U4.31)
PA7: MB1035 (P1.17), IO Peripherals (U5.3), STM32Fx (U4.32)
PA8: MB1035 (P2.45), STM32Fx (U4.67)
PA9: MB1035 (P2.44), STM32Fx (U4.68)
PA10: MB1035 (P2.43), STM32Fx (U4.69)
PA11: MB1035 (SB22.2), IO Peripherals (R18.2), STM32Fx (U4.70)
PA12: MB1035 (SB21.1), IO Peripherals (R17.2), STM32Fx (U4.71)
PA13: MB1035 (P2.40), ST_LINK_V2 (SB8.1), STM32Fx (U4.72)
PA14: MB1035 (P2.37), ST_LINK_V2 (SB3.1), STM32Fx (U4.76)
PA15: MB1035 (P2.38), STM32Fx (U4.77)
PB0: MB1035 (P1.22), STM32Fx (U4.35)
PB1: MB1035 (P1.21), STM32Fx (U4.36)
PB2: MB1035 (P1.24), STM32Fx (U4.37)
PB3: MB1035 (P2.26), ST_LINK_V2 (SB10.2), STM32Fx (U4.89)
PB4: MB1035 (P2.23), STM32Fx (U4.90)
PB5: MB1035 (P2.24), STM32Fx (U4.91)
PB6: MB1035 (P2.21), IO Peripherals (R28.2 U3.2), STM32Fx (U4.92)
PB7: MB1035 (P2.22), IO Peripherals (R27.2 U3.3), STM32Fx (U4.93)
PB8: MB1035 (P2.17), STM32Fx (U4.95)
PB9: MB1035 (P2.18), STM32Fx (U4.96)
PB10: MB1035 (P1.34), STM32Fx (U4.47)
PB11: MB1035 (P1.33), STM32Fx (U4.48)
PB12: MB1035 (P1.36), STM32Fx (U4.51)
PB13: MB1035 (P1.35), STM32Fx (U4.52)
PB14: MB1035 (P1.38), STM32Fx (U4.53)
PB15: MB1035 (P1.37), STM32Fx (U4.54)
PC0: MB1035 (P1.6), STM32Fx (U4.15)
PC1: MB1035 (P1.5), STM32Fx (U4.16)
PC2: MB1035 (P1.8), STM32Fx (U4.17)
PC3: MB1035 (P1.7), STM32Fx (U4.18)
PC4: MB1035 (P1.20), ST_LINK_V2 (SB15.1), STM32Fx (U4.33)
PC5: MB1035 (P1.19), ST_LINK_V2 (SB13.1), STM32Fx (U4.34)
PC6: MB1035 (P1.47), STM32Fx (U4.63)
PC7: MB1035 (P1.48), STM32Fx (U4.64)
PC8: MB1035 (P2.47), STM32Fx (U4.65)
PC9: MB1035 (P2.46), STM32Fx (U4.66)
PC10: MB1035 (P2.35), STM32Fx (U4.78)
PC11: MB1035 (P2.36), STM32Fx (U4.79)
PC12: MB1035 (P2.33), STM32Fx (U4.80)
PC13: MB1035 (P2.10), STM32Fx (U4.7)
PC14: MB1035 (P2.7), STM32Fx (SB14.1)
PC15: MB1035 (P2.8), STM32Fx (SB16.1)
PD0: MB1035 (P2.34), STM32Fx (U4.81)
PD1: MB1035 (P2.31), STM32Fx (U4.82)
PD2: MB1035 (P2.32), STM32Fx (U4.83)
PD3: MB1035 (P2.29), STM32Fx (U4.84)
PD4: MB1035 (P2.30), STM32Fx (U4.85)
PD5: MB1035 (P2.27), STM32Fx (U4.86)
PD6: MB1035 (P2.28), STM32Fx (U4.87)
PD7: MB1035 (P2.25), STM32Fx (U4.88)
PD8: MB1035 (P1.40), STM32Fx (U4.55)
PD9: MB1035 (P1.39), STM32Fx (U4.56)
PD10: MB1035 (P1.42), STM32Fx (U4.57)
PD11: MB1035 (P1.41), STM32Fx (U4.58)
PD12: MB1035 (P1.44), STM32Fx (U4.59)
PD13: MB1035 (P1.43), STM32Fx (U4.60)
PD14: MB1035 (P1.46), STM32Fx (U4.61)
PD15: MB1035 (P1.45), STM32Fx (U4.62)
PE0: MB1035 (P2.15), IO Peripherals (U5.7), STM32Fx (U4.97)
PE1: MB1035 (P2.16), IO Peripherals (U5.6), STM32Fx (U4.98)
PE2: MB1035 (P2.13), IO Peripherals (U3.9), STM32Fx (U4.1)
PE3: MB1035 (P2.14), IO Peripherals (U5.5), STM32Fx (U4.2)
PE4: MB1035 (P2.11), IO Peripherals (U3.5), STM32Fx (U4.3)
PE5: MB1035 (P2.12), IO Peripherals (U3.4), STM32Fx (U4.4)
PE6: MB1035 (P2.9), STM32Fx (U4.5)
PE7: MB1035 (P1.23), STM32Fx (U4.38)
PE8: MB1035 (P1.26), IO Peripherals (R40.2), STM32Fx (U4.39)
PE9: MB1035 (P1.25), IO Peripherals (R41.2), STM32Fx (U4.40)
PE10: MB1035 (P1.28), IO Peripherals (R42.2), STM32Fx (U4.41)
PE11: MB1035 (P1.27), IO Peripherals (R44.2), STM32Fx (U4.42)
PE12: MB1035 (P1.30), IO Peripherals (R47.2), STM32Fx (U4.43)
PE13: MB1035 (P1.29), IO Peripherals (R46.2), STM32Fx (U4.44)
PE14: MB1035 (P1.32), IO Peripherals (R45.2), STM32Fx (U4.45)
PE15: MB1035 (P1.31), IO Peripherals (R43.2), STM32Fx (U4.46)
PF0: MB1035 (P2.5), STM32Fx (SB17.1)
PF1: MB1035 (P2.6), STM32Fx (SB18.1)
PF2: MB1035 (P1.10), STM32Fx (U4.19)
PF4: MB1035 (P1.13), STM32Fx (U4.27)
PF6: MB1035 (P2.39), STM32Fx (U4.73)
PF9: MB1035 (P2.3), STM32Fx (U4.10)
PF10: MB1035 (P2.4), STM32Fx (U4.11)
